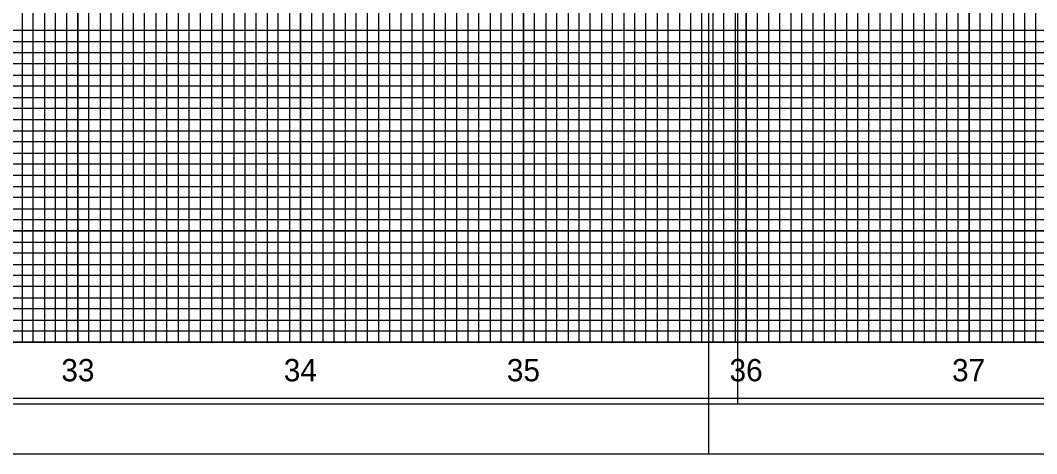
# Model space of a CAD drawing. Extents: x 2345490 to 2445302, y 465165 to 573888.
# Drawn here: x 2384041 to 2384497.1, y 500557.8 to 500752.4 of the extents above; entities that cross this region are included whole.
import ezdxf

# ---------------------------------------------------------------- set-up
doc = ezdxf.new("R2010")
doc.units = 0
for name, color, linetype in [('Exist Vertical Profile Horizontal Axis Label Major', 7, 'Continuous'), ('Old_Level_18', 7, 'Continuous'), ('Old_Level_41', 7, 'Continuous'), ('Old_Level_42', 7, 'Continuous'), ('Old_Level_43', 7, 'Continuous'), ('Old_Level_50', 7, 'Continuous'), ('Old_Level_51', 7, 'Continuous'), ('Old_Level_52', 7, 'Continuous'), ('Old_Level_57', 7, 'Continuous'), ('Old_Level_63', 7, 'Continuous')]:
    doc.layers.add(name, color=color, linetype=linetype)

msp = doc.modelspace()

# ---------------------------------------------------------------- linework, layer by layer
at = {"layer": 'Old_Level_18'}
msp.add_lwpolyline([(2384616.79875, 501632.775), (2383116.79875, 501632.775), (2383116.79875, 500582.775), (2384616.79875, 500582.775)], close=True, dxfattribs=at)
at = {"layer": 'Old_Level_41'}
msp.add_line((2384616.79875, 500607.775), (2383116.79875, 500607.775), dxfattribs=at)
for points in [[(2384041.79875, 501632.775), (2384041.79875, 500607.775), (2384091.79875, 500607.775), (2384091.79875, 501632.775)], [(2384066.79875, 501632.775), (2384066.79875, 500607.775), (2384116.79875, 500607.775), (2384116.79875, 501632.775)], [(2384141.79875, 501632.775), (2384141.79875, 500607.775), (2384191.79875, 500607.775), (2384191.79875, 501632.775)], [(2384166.79875, 501632.775), (2384166.79875, 500607.775), (2384216.79875, 500607.775), (2384216.79875, 501632.775)], [(2384241.79875, 501632.775), (2384241.79875, 500607.775), (2384291.79875, 500607.775), (2384291.79875, 501632.775)], [(2384266.79875, 501632.775), (2384266.79875, 500607.775), (2384316.79875, 500607.775), (2384316.79875, 501632.775)], [(2384341.79875, 501632.775), (2384341.79875, 500607.775), (2384391.79875, 500607.775), (2384391.79875, 501632.775)], [(2384366.79875, 501632.775), (2384366.79875, 500607.775), (2384416.79875, 500607.775), (2384416.79875, 501632.775)], [(2384441.79875, 501495.225), (2384441.79875, 500607.775), (2384491.79875, 500607.775), (2384491.79875, 501495.225)], [(2384616.79875, 500732.775), (2383116.79875, 500732.775), (2383116.79875, 500682.775), (2384616.79875, 500682.775)], [(2384616.79875, 500657.775), (2383116.79875, 500657.775), (2383116.79875, 500707.775), (2384616.79875, 500707.775)], [(2384616.79875, 500632.775), (2383116.79875, 500632.775)]]:
    msp.add_lwpolyline(points, dxfattribs=at)
at = {"layer": 'Old_Level_42'}
msp.add_lwpolyline([(2384466.79875, 501495.225), (2384466.79875, 500607.775), (2384516.79875, 500607.775), (2384516.79875, 501495.225)], dxfattribs=at)
at = {"layer": 'Old_Level_43'}
for points in [[(2384036.79875, 501632.775), (2384036.79875, 500607.775), (2384046.79875, 500607.775), (2384046.79875, 501632.775)], [(2384051.79875, 501632.775), (2384051.79875, 500607.775), (2384056.79875, 500607.775), (2384056.79875, 501632.775)], [(2384061.79875, 501632.775), (2384061.79875, 500607.775), (2384071.79875, 500607.775), (2384071.79875, 501632.775)], [(2384076.79875, 501632.775), (2384076.79875, 500607.775), (2384081.79875, 500607.775), (2384081.79875, 501632.775)], [(2384086.79875, 501632.775), (2384086.79875, 500607.775), (2384096.79875, 500607.775), (2384096.79875, 501632.775)], [(2384101.79875, 501632.775), (2384101.79875, 500607.775), (2384106.79875, 500607.775), (2384106.79875, 501632.775)], [(2384111.79875, 501632.775), (2384111.79875, 500607.775), (2384121.79875, 500607.775), (2384121.79875, 501632.775)], [(2384126.79875, 501632.775), (2384126.79875, 500607.775), (2384131.79875, 500607.775), (2384131.79875, 501632.775)], [(2384136.79875, 501632.775), (2384136.79875, 500607.775), (2384146.79875, 500607.775), (2384146.79875, 501632.775)], [(2384151.79875, 501632.775), (2384151.79875, 500607.775), (2384156.79875, 500607.775), (2384156.79875, 501632.775)], [(2384161.79875, 501632.775), (2384161.79875, 500607.775), (2384171.79875, 500607.775), (2384171.79875, 501632.775)], [(2384176.79875, 501632.775), (2384176.79875, 500607.775), (2384181.79875, 500607.775), (2384181.79875, 501632.775)], [(2384186.79875, 501632.775), (2384186.79875, 500607.775)], [(2384186.79875, 500607.775), (2384196.79875, 500607.775), (2384196.79875, 501632.775)], [(2384201.79875, 501632.775), (2384201.79875, 500607.775), (2384206.79875, 500607.775), (2384206.79875, 501632.775)], [(2384211.79875, 501632.775), (2384211.79875, 500607.775), (2384221.79875, 500607.775), (2384221.79875, 501632.775)], [(2384226.79875, 501632.775), (2384226.79875, 500607.775), (2384231.79875, 500607.775), (2384231.79875, 501632.775)], [(2384236.79875, 501632.775), (2384236.79875, 500607.775), (2384246.79875, 500607.775), (2384246.79875, 501632.775)], [(2384251.79875, 501632.775), (2384251.79875, 500607.775), (2384256.79875, 500607.775), (2384256.79875, 501632.775)], [(2384261.79875, 501632.775), (2384261.79875, 500607.775), (2384271.79875, 500607.775), (2384271.79875, 501632.775)], [(2384276.79875, 501632.775), (2384276.79875, 500607.775), (2384281.79875, 500607.775), (2384281.79875, 501632.775)], [(2384286.79875, 501632.775), (2384286.79875, 500607.775), (2384296.79875, 500607.775), (2384296.79875, 501632.775)], [(2384301.79875, 501632.775), (2384301.79875, 500607.775), (2384306.79875, 500607.775), (2384306.79875, 501632.775)], [(2384311.79875, 501632.775), (2384311.79875, 500607.775), (2384321.79875, 500607.775), (2384321.79875, 501632.775)], [(2384326.79875, 501632.775), (2384326.79875, 500607.775), (2384331.79875, 500607.775), (2384331.79875, 501632.775)], [(2384336.79875, 501632.775), (2384336.79875, 500607.775), (2384346.79875, 500607.775), (2384346.79875, 501632.775)], [(2384351.79875, 501632.775), (2384351.79875, 500607.775), (2384356.79875, 500607.775), (2384356.79875, 501632.775)], [(2384361.79875, 501632.775), (2384361.79875, 500607.775), (2384371.79875, 500607.775), (2384371.79875, 501632.775)], [(2384376.79875, 501632.775), (2384376.79875, 500607.775), (2384381.79875, 500607.775), (2384381.79875, 501632.775)], [(2384386.79875, 501632.775), (2384386.79875, 500607.775), (2384396.79875, 500607.775), (2384396.79875, 501632.775)], [(2384401.79875, 501632.775), (2384401.79875, 500607.775), (2384406.79875, 500607.775), (2384406.79875, 501632.775)], [(2384411.79875, 501632.775), (2384411.79875, 500607.775), (2384421.79875, 500607.775), (2384421.79875, 501495.225)], [(2384426.79875, 501495.225), (2384426.79875, 500607.775), (2384431.79875, 500607.775), (2384431.79875, 501495.225)], [(2384436.79875, 501495.225), (2384436.79875, 500607.775), (2384446.79875, 500607.775), (2384446.79875, 501495.225)], [(2384451.79875, 501495.225), (2384451.79875, 500607.775), (2384456.79875, 500607.775), (2384456.79875, 501495.225)], [(2384461.79875, 501495.225), (2384461.79875, 500607.775), (2384471.79875, 500607.775), (2384471.79875, 501495.225)], [(2384476.79875, 501495.225), (2384476.79875, 500607.775), (2384481.79875, 500607.775), (2384481.79875, 501495.225)], [(2384486.79875, 501495.225), (2384486.79875, 500607.775), (2384496.79875, 500607.775), (2384496.79875, 501495.225)], [(2384566.79875, 500747.775), (2383166.79875, 500747.775), (2383166.79875, 500742.775), (2384566.79875, 500742.775)], [(2384566.79875, 500737.775), (2383166.79875, 500737.775), (2383166.79875, 500727.775), (2384566.79875, 500727.775)], [(2384566.79875, 500722.775), (2383166.79875, 500722.775), (2383166.79875, 500717.775), (2384566.79875, 500717.775)], [(2384566.79875, 500712.775), (2383166.79875, 500712.775), (2383166.79875, 500702.775), (2384566.79875, 500702.775)], [(2384566.79875, 500697.775), (2383166.79875, 500697.775), (2383166.79875, 500692.775), (2384566.79875, 500692.775)], [(2384566.79875, 500687.775), (2383166.79875, 500687.775), (2383166.79875, 500677.775), (2384566.79875, 500677.775)], [(2384566.79875, 500672.775), (2383166.79875, 500672.775), (2383166.79875, 500667.775), (2384566.79875, 500667.775)], [(2384566.79875, 500662.775), (2383166.79875, 500662.775), (2383166.79875, 500652.775), (2384566.79875, 500652.775)], [(2384566.79875, 500647.775), (2383166.79875, 500647.775), (2383166.79875, 500642.775), (2384566.79875, 500642.775)], [(2384566.79875, 500637.775), (2383166.79875, 500637.775), (2383166.79875, 500627.775), (2384566.79875, 500627.775)], [(2384566.79875, 500622.775), (2383166.79875, 500622.775), (2383166.79875, 500617.775), (2384566.79875, 500617.775)], [(2384566.79875, 500612.775), (2383166.79875, 500612.775)]]:
    msp.add_lwpolyline(points, dxfattribs=at)
at = {"layer": 'Old_Level_50'}
msp.add_line((2384349.79875, 500557.775), (2384349.79875, 500557.775), dxfattribs=at)
for points in [[(2384629.29875, 501635.325), (2382962.79875, 501635.325), (2382962.79875, 500580.225), (2384629.29875, 500580.225)], [(2386029.29875, 501635.325), (2384362.79875, 501635.325), (2384362.79875, 500580.225), (2386029.29875, 500580.225)]]:
    msp.add_lwpolyline(points, close=True, dxfattribs=at)
at = {"layer": 'Old_Level_51'}
for points in [[(2384633.79875, 501657.775), (2382949.79875, 501657.775), (2382949.79875, 500557.775), (2384633.79875, 500557.775)], [(2386033.79875, 501657.775), (2384349.79875, 501657.775), (2384349.79875, 500557.775), (2386033.79875, 500557.775)]]:
    msp.add_lwpolyline(points, close=True, dxfattribs=at)
at = {"layer": 'Old_Level_52'}
msp.add_line((2384362.79875, 500580.225), (2384362.79875, 500580.225), dxfattribs=at)
at = {"layer": 'Old_Level_57'}
for p, q in [((2384066.79875, 500607.77525), (2384066.79875, 501057.77525)), ((2384066.79875, 500607.87525), (2384066.79875, 501057.77525)), ((2384166.79875, 500607.77525), (2384166.79875, 501057.77525)), ((2384166.79875, 500607.87525), (2384166.79875, 501057.77525)), ((2384266.79875, 500607.77525), (2384266.79875, 501057.77525)), ((2384266.79875, 500607.87525), (2384266.79875, 501057.77525)), ((2384366.79875, 500607.77525), (2384366.79875, 501057.77525)), ((2384366.79875, 500607.87525), (2384366.79875, 501057.77525)), ((2384466.79875, 500607.77525), (2384466.79875, 501057.77525)), ((2384466.79875, 500607.87525), (2384466.79875, 501057.77525)), ((2381716.79925, 500707.77525), (2385066.79875, 500707.77525)), ((2381716.799, 500657.77525), (2385066.79875, 500657.77525)), ((2381716.79925, 500607.77525), (2385066.79875, 500607.77525))]:
    msp.add_line(p, q, dxfattribs=at)
at = {"layer": 'Old_Level_63'}
msp.add_line((2381766.79875, 500607.775), (2384797.7405, 500607.775), dxfattribs=at)

# ---------------------------------------------------------------- texts
at = {"layer": 'Exist Vertical Profile Horizontal Axis Label Major'}
for s, p in [('33', (2384059.40789, 500590.275)), ('34', (2384159.25032, 500590.275)), ('35', (2384259.34274, 500590.275)), ('36', (2384359.28365, 500590.275)), ('37', (2384459.14122, 500590.275))]:
    msp.add_text(s, height=10, dxfattribs=at).set_placement(p)

doc.saveas('drawing.dxf')
